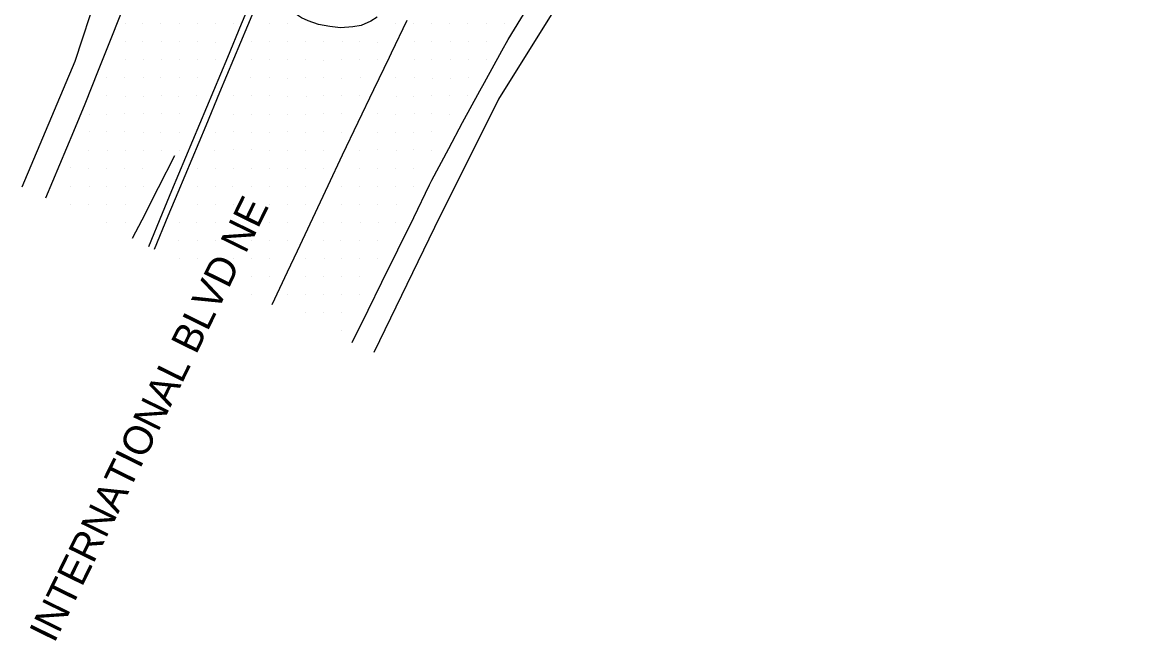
# Model space of a CAD drawing. Extents: x 2244337 to 2251208, y 199469 to 202984.
# Drawn here: x 2245377.3 to 2245531.4, y 202094.8 to 202180.4 of the extents above; entities that cross this region are included whole.
import ezdxf

# ---------------------------------------------------------------- set-up
doc = ezdxf.new("R2010")
doc.units = 0
for name, color, linetype in [('Exist DTM Scan Elevation Point', 7, 'Continuous'), ('Exist Roads EOP', 7, 'Continuous'), ('Exist Roads EOT', 7, 'Continuous'), ('Exist Roads Text', 7, 'Continuous')]:
    doc.layers.add(name, color=color, linetype=linetype)

msp = doc.modelspace()

# ---------------------------------------------------------------- linework, layer by layer
at = {"layer": 'Exist DTM Scan Elevation Point'}
for p, q in [((2245394.06, 202180.22), (2245394.06, 202180.22)), ((2245396.5, 202180.22), (2245396.5, 202180.22)), ((2245399.09, 202180.23), (2245399.09, 202180.23)), ((2245401.6, 202180.23), (2245401.6, 202180.23)), ((2245404.05, 202180.27), (2245404.05, 202180.27)), ((2245414.06, 202180.23), (2245414.06, 202180.23)), ((2245436.57, 202180.22), (2245436.57, 202180.22)), ((2245439.04, 202180.29), (2245439.04, 202180.29)), ((2245441.58, 202180.23), (2245441.58, 202180.23)), ((2245391.6, 202180.2), (2245391.6, 202180.2)), ((2245406.62, 202180.21), (2245406.62, 202180.21)), ((2245411.58, 202180.19), (2245411.58, 202180.19)), ((2245429.07, 202180.18), (2245429.07, 202180.18)), ((2245431.57, 202180.19), (2245431.57, 202180.19)), ((2245434.05, 202180.18), (2245434.05, 202180.18)), ((2245444.06, 202180.21), (2245444.06, 202180.21)), ((2245391.61, 202177.73), (2245391.61, 202177.73)), ((2245394.06, 202177.69), (2245394.06, 202177.69)), ((2245396.58, 202177.73), (2245396.58, 202177.73)), ((2245399.07, 202177.72), (2245399.07, 202177.72)), ((2245401.57, 202177.71), (2245401.57, 202177.71)), ((2245404.11, 202177.67), (2245404.11, 202177.67)), ((2245409.07, 202177.69), (2245409.07, 202177.69)), ((2245411.59, 202177.72), (2245411.59, 202177.72)), ((2245414.08, 202177.73), (2245414.08, 202177.73)), ((2245416.59, 202177.73), (2245416.59, 202177.73)), ((2245419.05, 202177.73), (2245419.05, 202177.73)), ((2245421.64, 202177.7), (2245421.64, 202177.7)), ((2245424.07, 202177.72), (2245424.07, 202177.72)), ((2245426.55, 202177.67), (2245426.55, 202177.67)), ((2245431.63, 202177.73), (2245431.63, 202177.73)), ((2245434.07, 202177.7), (2245434.07, 202177.7)), ((2245436.58, 202177.7), (2245436.58, 202177.7)), ((2245439.09, 202177.75), (2245439.09, 202177.75)), ((2245441.58, 202177.72), (2245441.58, 202177.72)), ((2245391.6, 202175.2), (2245391.6, 202175.2)), ((2245394.1, 202175.25), (2245394.1, 202175.25)), ((2245396.59, 202175.2), (2245396.59, 202175.2)), ((2245399.12, 202175.2), (2245399.12, 202175.2)), ((2245401.58, 202175.2), (2245401.58, 202175.2)), ((2245404.11, 202175.21), (2245404.11, 202175.21)), ((2245409.02, 202175.21), (2245409.02, 202175.21)), ((2245411.59, 202175.25), (2245411.59, 202175.25)), ((2245414.1, 202175.23), (2245414.1, 202175.23)), ((2245416.57, 202175.22), (2245416.57, 202175.22)), ((2245419.09, 202175.18), (2245419.09, 202175.18)), ((2245421.57, 202175.23), (2245421.57, 202175.23)), ((2245424.1, 202175.21), (2245424.1, 202175.21)), ((2245426.56, 202175.2), (2245426.56, 202175.2)), ((2245431.6, 202175.19), (2245431.6, 202175.19)), ((2245434.07, 202175.22), (2245434.07, 202175.22)), ((2245436.58, 202175.26), (2245436.58, 202175.26)), ((2245439.08, 202175.2), (2245439.08, 202175.2)), ((2245441.56, 202175.21), (2245441.56, 202175.21)), ((2245389.07, 202172.76), (2245389.07, 202172.76)), ((2245391.57, 202172.73), (2245391.57, 202172.73)), ((2245394.07, 202172.7), (2245394.07, 202172.7)), ((2245396.55, 202172.71), (2245396.55, 202172.71)), ((2245399.06, 202172.74), (2245399.06, 202172.74)), ((2245401.58, 202172.7), (2245401.58, 202172.7)), ((2245409.01, 202172.72), (2245409.01, 202172.72)), ((2245411.59, 202172.72), (2245411.59, 202172.72)), ((2245414.1, 202172.67), (2245414.1, 202172.67)), ((2245416.62, 202172.7), (2245416.62, 202172.7)), ((2245419.05, 202172.7), (2245419.05, 202172.7)), ((2245421.55, 202172.69), (2245421.55, 202172.69)), ((2245424.13, 202172.72), (2245424.13, 202172.72)), ((2245429.09, 202172.73), (2245429.09, 202172.73)), ((2245431.62, 202172.71), (2245431.62, 202172.71)), ((2245434.1, 202172.68), (2245434.1, 202172.68)), ((2245436.63, 202172.68), (2245436.63, 202172.68)), ((2245439.07, 202172.72), (2245439.07, 202172.72)), ((2245389.08, 202170.21), (2245389.08, 202170.21)), ((2245391.6, 202170.18), (2245391.6, 202170.18)), ((2245394.1, 202170.2), (2245394.1, 202170.2)), ((2245396.59, 202170.21), (2245396.59, 202170.21)), ((2245399.05, 202170.18), (2245399.05, 202170.18)), ((2245401.53, 202170.23), (2245401.53, 202170.23)), ((2245406.57, 202170.23), (2245406.57, 202170.23)), ((2245409.07, 202170.21), (2245409.07, 202170.21)), ((2245411.54, 202170.22), (2245411.54, 202170.22)), ((2245414.13, 202170.19), (2245414.13, 202170.19)), ((2245416.64, 202170.2), (2245416.64, 202170.2)), ((2245419.08, 202170.22), (2245419.08, 202170.22)), ((2245421.55, 202170.21), (2245421.55, 202170.21)), ((2245424.08, 202170.21), (2245424.08, 202170.21)), ((2245429.1, 202170.19), (2245429.1, 202170.19)), ((2245431.54, 202170.15), (2245431.54, 202170.15)), ((2245434.07, 202170.21), (2245434.07, 202170.21)), ((2245436.57, 202170.22), (2245436.57, 202170.22)), ((2245439.06, 202170.23), (2245439.06, 202170.23)), ((2245386.61, 202167.67), (2245386.61, 202167.67)), ((2245389.08, 202167.7), (2245389.08, 202167.7)), ((2245391.55, 202167.72), (2245391.55, 202167.72)), ((2245394.11, 202167.72), (2245394.11, 202167.72)), ((2245396.58, 202167.74), (2245396.58, 202167.74)), ((2245399.1, 202167.75), (2245399.1, 202167.75)), ((2245406.58, 202167.7), (2245406.58, 202167.7)), ((2245409.08, 202167.71), (2245409.08, 202167.71)), ((2245411.58, 202167.69), (2245411.58, 202167.69)), ((2245414.1, 202167.7), (2245414.1, 202167.7)), ((2245416.55, 202167.7), (2245416.55, 202167.7)), ((2245419, 202167.77), (2245419, 202167.77)), ((2245421.57, 202167.74), (2245421.57, 202167.74)), ((2245426.57, 202167.72), (2245426.57, 202167.72)), ((2245429.06, 202167.7), (2245429.06, 202167.7)), ((2245431.6, 202167.73), (2245431.6, 202167.73)), ((2245434.06, 202167.73), (2245434.06, 202167.73)), ((2245436.57, 202167.66), (2245436.57, 202167.66)), ((2245386.62, 202165.22), (2245386.62, 202165.22)), ((2245389.03, 202165.24), (2245389.03, 202165.24)), ((2245391.57, 202165.22), (2245391.57, 202165.22)), ((2245394.07, 202165.21), (2245394.07, 202165.21)), ((2245396.54, 202165.21), (2245396.54, 202165.21)), ((2245399.1, 202165.2), (2245399.1, 202165.2)), ((2245404.04, 202165.21), (2245404.04, 202165.21)), ((2245406.62, 202165.23), (2245406.62, 202165.23)), ((2245409.1, 202165.2), (2245409.1, 202165.2)), ((2245411.55, 202165.18), (2245411.55, 202165.18)), ((2245414.06, 202165.24), (2245414.06, 202165.24)), ((2245416.59, 202165.18), (2245416.59, 202165.18)), ((2245419.08, 202165.22), (2245419.08, 202165.22)), ((2245421.6, 202165.19), (2245421.6, 202165.19)), ((2245426.58, 202165.21), (2245426.58, 202165.21)), ((2245429.09, 202165.21), (2245429.09, 202165.21)), ((2245431.58, 202165.18), (2245431.58, 202165.18)), ((2245434.02, 202165.25), (2245434.02, 202165.25)), ((2245386.54, 202162.67), (2245386.54, 202162.67)), ((2245389.11, 202162.7), (2245389.11, 202162.7)), ((2245391.58, 202162.72), (2245391.58, 202162.72)), ((2245394.11, 202162.7), (2245394.11, 202162.7)), ((2245396.58, 202162.7), (2245396.58, 202162.7)), ((2245399.11, 202162.68), (2245399.11, 202162.68)), ((2245404.02, 202162.7), (2245404.02, 202162.7)), ((2245406.56, 202162.75), (2245406.56, 202162.75)), ((2245409.11, 202162.74), (2245409.11, 202162.74)), ((2245411.63, 202162.71), (2245411.63, 202162.71)), ((2245414.11, 202162.68), (2245414.11, 202162.68)), ((2245416.54, 202162.71), (2245416.54, 202162.71)), ((2245419.1, 202162.7), (2245419.1, 202162.7)), ((2245424.09, 202162.72), (2245424.09, 202162.72)), ((2245426.57, 202162.77), (2245426.57, 202162.77)), ((2245429.1, 202162.72), (2245429.1, 202162.72)), ((2245431.58, 202162.73), (2245431.58, 202162.73)), ((2245434.05, 202162.72), (2245434.05, 202162.72)), ((2245384.02, 202160.24), (2245384.02, 202160.24)), ((2245386.56, 202160.23), (2245386.56, 202160.23)), ((2245389.05, 202160.2), (2245389.05, 202160.2)), ((2245391.56, 202160.2), (2245391.56, 202160.2)), ((2245401.6, 202160.22), (2245401.6, 202160.22)), ((2245404.09, 202160.22), (2245404.09, 202160.22)), ((2245406.58, 202160.21), (2245406.58, 202160.21)), ((2245414.09, 202160.23), (2245414.09, 202160.23)), ((2245416.6, 202160.21), (2245416.6, 202160.21)), ((2245419.07, 202160.21), (2245419.07, 202160.21)), ((2245424.08, 202160.23), (2245424.08, 202160.23)), ((2245426.58, 202160.22), (2245426.58, 202160.22)), ((2245429.08, 202160.2), (2245429.08, 202160.2)), ((2245431.56, 202160.19), (2245431.56, 202160.19)), ((2245394.05, 202160.18), (2245394.05, 202160.18)), ((2245409.06, 202160.18), (2245409.06, 202160.18)), ((2245411.61, 202160.17), (2245411.61, 202160.17)), ((2245384.07, 202157.69), (2245384.07, 202157.69)), ((2245386.59, 202157.68), (2245386.59, 202157.68)), ((2245389.08, 202157.7), (2245389.08, 202157.7)), ((2245391.59, 202157.72), (2245391.59, 202157.72)), ((2245394.1, 202157.71), (2245394.1, 202157.71)), ((2245401.57, 202157.68), (2245401.57, 202157.68)), ((2245404.07, 202157.68), (2245404.07, 202157.68)), ((2245406.51, 202157.68), (2245406.51, 202157.68)), ((2245409.05, 202157.68), (2245409.05, 202157.68)), ((2245411.59, 202157.7), (2245411.59, 202157.7)), ((2245414.11, 202157.65), (2245414.11, 202157.65)), ((2245416.52, 202157.74), (2245416.52, 202157.74)), ((2245421.57, 202157.73), (2245421.57, 202157.73)), ((2245424.09, 202157.74), (2245424.09, 202157.74)), ((2245426.59, 202157.69), (2245426.59, 202157.69)), ((2245429.02, 202157.69), (2245429.02, 202157.69)), ((2245431.57, 202157.72), (2245431.57, 202157.72)), ((2245384.09, 202155.21), (2245384.09, 202155.21)), ((2245386.54, 202155.23), (2245386.54, 202155.23)), ((2245389.03, 202155.2), (2245389.03, 202155.2)), ((2245391.61, 202155.22), (2245391.61, 202155.22)), ((2245401.57, 202155.22), (2245401.57, 202155.22)), ((2245404.09, 202155.23), (2245404.09, 202155.23)), ((2245406.55, 202155.17), (2245406.55, 202155.17)), ((2245409.05, 202155.2), (2245409.05, 202155.2)), ((2245411.54, 202155.23), (2245411.54, 202155.23)), ((2245414.11, 202155.24), (2245414.11, 202155.24)), ((2245416.57, 202155.25), (2245416.57, 202155.25)), ((2245421.59, 202155.19), (2245421.59, 202155.19)), ((2245424.11, 202155.19), (2245424.11, 202155.19)), ((2245426.55, 202155.24), (2245426.55, 202155.24)), ((2245429.1, 202155.2), (2245429.1, 202155.2)), ((2245389.07, 202152.71), (2245389.07, 202152.71)), ((2245391.59, 202152.7), (2245391.59, 202152.7)), ((2245399.06, 202152.7), (2245399.06, 202152.7)), ((2245401.54, 202152.7), (2245401.54, 202152.7)), ((2245404.11, 202152.69), (2245404.11, 202152.69)), ((2245406.61, 202152.75), (2245406.61, 202152.75)), ((2245409.09, 202152.72), (2245409.09, 202152.72)), ((2245411.57, 202152.7), (2245411.57, 202152.7)), ((2245414.09, 202152.71), (2245414.09, 202152.71)), ((2245419.1, 202152.71), (2245419.1, 202152.71)), ((2245421.5, 202152.7), (2245421.5, 202152.7)), ((2245424.16, 202152.71), (2245424.16, 202152.71)), ((2245426.61, 202152.71), (2245426.61, 202152.71)), ((2245429.07, 202152.73), (2245429.07, 202152.73)), ((2245399.05, 202150.21), (2245399.05, 202150.21)), ((2245401.57, 202150.25), (2245401.57, 202150.25)), ((2245404.08, 202150.18), (2245404.08, 202150.18)), ((2245406.58, 202150.25), (2245406.58, 202150.25)), ((2245409.09, 202150.24), (2245409.09, 202150.24)), ((2245411.55, 202150.2), (2245411.55, 202150.2)), ((2245414.07, 202150.23), (2245414.07, 202150.23)), ((2245419.11, 202150.21), (2245419.11, 202150.21)), ((2245421.48, 202150.24), (2245421.48, 202150.24)), ((2245424.1, 202150.24), (2245424.1, 202150.24)), ((2245426.58, 202150.22), (2245426.58, 202150.22)), ((2245399.11, 202147.72), (2245399.11, 202147.72)), ((2245401.56, 202147.73), (2245401.56, 202147.73)), ((2245404.11, 202147.69), (2245404.11, 202147.69)), ((2245406.59, 202147.74), (2245406.59, 202147.74)), ((2245409.09, 202147.68), (2245409.09, 202147.68)), ((2245411.57, 202147.69), (2245411.57, 202147.69)), ((2245416.63, 202147.75), (2245416.63, 202147.75)), ((2245419.13, 202147.72), (2245419.13, 202147.72)), ((2245421.56, 202147.75), (2245421.56, 202147.75)), ((2245424.07, 202147.7), (2245424.07, 202147.7)), ((2245426.56, 202147.69), (2245426.56, 202147.69)), ((2245404.07, 202145.18), (2245404.07, 202145.18)), ((2245406.58, 202145.21), (2245406.58, 202145.21)), ((2245409.05, 202145.22), (2245409.05, 202145.22)), ((2245411.54, 202145.19), (2245411.54, 202145.19)), ((2245416.54, 202145.22), (2245416.54, 202145.22)), ((2245419.08, 202145.2), (2245419.08, 202145.2)), ((2245421.6, 202145.17), (2245421.6, 202145.17)), ((2245424.07, 202145.2), (2245424.07, 202145.2)), ((2245409.09, 202142.69), (2245409.09, 202142.69)), ((2245414.11, 202142.71), (2245414.11, 202142.71)), ((2245416.58, 202142.74), (2245416.58, 202142.74)), ((2245419.1, 202142.71), (2245419.1, 202142.71)), ((2245421.61, 202142.71), (2245421.61, 202142.71)), ((2245424.06, 202142.74), (2245424.06, 202142.74)), ((2245416.54, 202140.19), (2245416.54, 202140.19)), ((2245419.06, 202140.18), (2245419.06, 202140.18)), ((2245421.6, 202140.23), (2245421.6, 202140.23)), ((2245421.56, 202137.71), (2245421.56, 202137.71))]:
    msp.add_line(p, q, dxfattribs=at)
at = {"layer": 'Exist Roads EOP'}
for points in [[(2245659.8, 202192.5), (2245645.83, 202197.41), (2245631.9, 202202.82), (2245617.79, 202207.92), (2245603.76, 202213.11), (2245589.73, 202218.46), (2245575.53, 202223.21), (2245561.31, 202227.62), (2245546.92, 202231.67), (2245532.75, 202234.7), (2245526.89, 202234.51), (2245512.9, 202231.99), (2245499.38, 202228.23), (2245487.58, 202221.59), (2245476.36, 202212.36), (2245465.98, 202202.35), (2245456.75, 202190.86), (2245453.82, 202186.64), (2245443.29, 202169.76), (2245434.41, 202151.99), (2245426.03, 202134.68)], [(2245377.35, 202157.65), (2245384.68, 202175.04), (2245390.88, 202193.88), (2245394.96, 202206.8), (2245399.62, 202224.5)], [(2245426.5, 202181.13), (2245425.61, 202180.54), (2245424.29, 202179.98), (2245423.13, 202179.77), (2245421.42, 202179.64), (2245419.95, 202179.8), (2245418.38, 202180.08), (2245416.95, 202180.6), (2245416.01, 202181.01), (2245415.05, 202181.68), (2245414.38, 202182.42), (2245413.63, 202183.38), (2245413.2, 202184.23), (2245412.68, 202185.56), (2245412.44, 202186.29), (2245412.24, 202187.2), (2245412.2, 202188.74), (2245412.33, 202190.02), (2245412.61, 202191.13)]]:
    msp.add_lwpolyline(points, dxfattribs=at)
at = {"layer": 'Exist Roads EOT'}
for points in [[(2245394.86, 202149.39), (2245396.78, 202154), (2245398.08, 202157.11), (2245400.01, 202161.72), (2245401.94, 202166.33), (2245403.87, 202170.95), (2245405.8, 202175.56), (2245407.72, 202180.17), (2245409.65, 202184.79)], [(2245395.64, 202149.02), (2245397.57, 202153.63), (2245398.93, 202156.88), (2245400.86, 202161.49), (2245402.79, 202166.11), (2245404.72, 202170.72), (2245406.64, 202175.33), (2245408.57, 202179.94), (2245410.49, 202184.53)], [(2245380.59, 202156.11), (2245382.53, 202160.72), (2245384.47, 202165.33), (2245386.06, 202169.11), (2245387.9, 202173.76), (2245389.75, 202178.4), (2245391.6, 202183.05)], [(2245423.04, 202136.09), (2245425.25, 202140.58), (2245427.14, 202144.43), (2245429.34, 202148.91), (2245431.55, 202153.4), (2245433.75, 202157.89), (2245434.07, 202158.53), (2245436.4, 202162.95), (2245438.3, 202166.55), (2245440.7, 202170.93), (2245441.33, 202172.07), (2245443.76, 202176.44), (2245444.63, 202178.01), (2245447.26, 202182.3)], [(2245411.94, 202141.33), (2245414.07, 202145.85), (2245415.44, 202148.77), (2245417.57, 202153.3), (2245419.69, 202157.82), (2245421.69, 202162.07), (2245423.86, 202166.58), (2245426.02, 202171.09), (2245428.18, 202175.6), (2245428.47, 202176.2), (2245430.62, 202180.71)], [(2245398.45, 202161.93), (2245396.17, 202157.48), (2245393.89, 202153.03), (2245392.58, 202150.46)]]:
    msp.add_lwpolyline(points, dxfattribs=at)

# ---------------------------------------------------------------- texts
at = {"layer": 'Exist Roads Text'}
msp.add_text('INTERNATIONAL BLVD NE', height=4.02, rotation=63.8338, dxfattribs=at).set_placement((2245381.78, 202094.35))

doc.saveas('drawing.dxf')
